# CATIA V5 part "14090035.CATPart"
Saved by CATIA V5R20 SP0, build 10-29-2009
Part number: 14090035
Definition: NONE
Nomenclature: 14090035
Source: Unknown
Description: 14090035
Bounding box of the stored display mesh (mm): x -17.5 to 70, y -59 to 49.1, z -49.1 to 49.1
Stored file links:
  C:\Users\Utente\Desktop\IO LAVORO\3D X SITO CF\X SITO\PLASTICA\RF2\14090035.CATPart
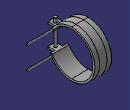
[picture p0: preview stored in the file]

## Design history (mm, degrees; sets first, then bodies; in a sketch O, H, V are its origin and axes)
Body1 "14090035" (main body)
  Solid1: solid without history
